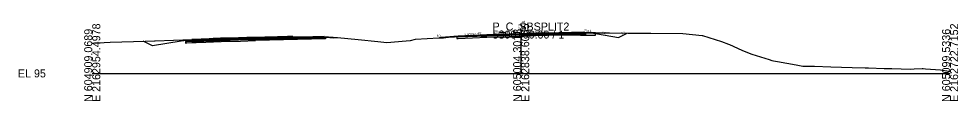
# Model space of a CAD drawing. Extents: x -26 to 1303, y -10 to 12033.
# Drawn here: x -25.7 to 302.8, y 10490.3 to 10518.4 of the extents above; entities that cross this region are included whole.
import ezdxf

# ---------------------------------------------------------------- set-up
doc = ezdxf.new("R2010")
doc.units = 0
for name, color, linetype in [('RD_GPK_XS_Cell', 7, 'Continuous'), ('RD_XS_Base', 7, 'Continuous'), ('RD_XS_ExGround', 7, 'Continuous'), ('RD_XS_ExPaveRet', 7, 'Continuous'), ('RD_XS_Greenside', 7, 'Continuous'), ('RD_XS_Pave', 7, 'Continuous'), ('RD_XS_PaveOvlay_CP', 7, 'Continuous'), ('RD_XS_TieSlope', 7, 'Continuous'), ('RD_XS_TX_Elev_EX', 7, 'Continuous'), ('RD_XS_TX_Elev_PR', 7, 'Continuous'), ('RD_XS_TX_ShdSlope', 7, 'Continuous'), ('RD_XS_TX_Slope', 7, 'Continuous')]:
    doc.layers.add(name, color=color, linetype=linetype)

msp = doc.modelspace()

# ---------------------------------------------------------------- linework, layer by layer
at = {"layer": 'RD_GPK_XS_Cell'}
for p, q in [((150, 10500), (150, 10515)), ((0, 10500), (150, 10500)), ((150, 10500), (300, 10500))]:
    msp.add_line(p, q, dxfattribs=at)
at = {"layer": 'RD_XS_Base'}
for p, q in [((138, 10513.16), (128, 10512.76)), ((136, 10513.08), (136, 10513.08)), ((150, 10513.49), (138, 10513.16)), ((150, 10513.49), (172, 10514.11)), ((150, 10512.99), (150, 10513.65)), ((150, 10513.65), (150, 10513.65)), ((150, 10513.65), (150, 10513.65)), ((150, 10513.65), (150, 10513.49)), ((172.5, 10513.62), (150, 10512.99)), ((150, 10513.49), (150, 10513.49)), ((150, 10512.99), (150, 10513.49)), ((150, 10513.49), (150, 10513.49)), ((150, 10513.49), (150, 10513.49)), ((162, 10513.83), (162, 10513.83)), ((162, 10513.83), (162, 10513.83)), ((162, 10513.33), (162, 10513.33)), ((162, 10513.33), (162, 10513.33)), ((172, 10514.11), (172, 10514.11)), ((172.5, 10514.12), (172.5, 10513.62)), ((172.5, 10514.09), (172.5, 10514.09)), ((32.89, 10511.16), (32.61, 10511.14)), ((32.61, 10511.14), (32.61, 10510.92)), ((32.61, 10510.92), (32.61, 10510.64)), ((32.61, 10510.64), (32.89, 10510.66)), ((33.11, 10511.16), (32.89, 10511.16)), ((32.89, 10510.66), (33.11, 10510.66)), ((39.76, 10511.43), (33.11, 10511.16)), ((33.11, 10510.66), (39.76, 10510.93)), ((45.11, 10511.64), (39.76, 10511.43)), ((39.76, 10510.93), (45.11, 10511.14)), ((51.86, 10511.82), (45.11, 10511.64)), ((45.11, 10511.14), (51.86, 10511.32)), ((57.11, 10511.96), (51.86, 10511.82)), ((51.86, 10511.32), (57.11, 10511.46)), ((57.11, 10511.96), (81.61, 10512.59)), ((57.11, 10511.46), (57.11, 10512.11)), ((57.11, 10512.11), (57.11, 10512.11)), ((57.11, 10512.11), (57.11, 10512.11)), ((57.11, 10512.11), (57.11, 10511.96)), ((81.61, 10512.09), (57.11, 10511.46)), ((57.11, 10511.96), (57.11, 10511.96)), ((57.11, 10511.46), (57.11, 10511.96)), ((57.11, 10511.96), (57.11, 10511.96)), ((57.11, 10511.96), (57.11, 10511.96)), ((57.11, 10511.46), (57.11, 10511.46)), ((81.11, 10512.58), (81.11, 10512.58)), ((81.11, 10512.58), (81.11, 10512.58)), ((81.11, 10512.58), (81.11, 10512.58)), ((81.11, 10512.08), (81.11, 10512.08)), ((81.11, 10512.08), (81.11, 10512.08)), ((81.61, 10512.59), (81.61, 10512.09)), ((81.61, 10512.56), (81.61, 10512.56)), ((128, 10512.76), (127.5, 10512.74)), ((127.5, 10512.74), (127.5, 10512.74)), ((127.5, 10512.74), (127.5, 10512.24)), ((127.5, 10512.24), (128, 10512.26)), ((128, 10512.76), (128, 10512.76)), ((128, 10512.26), (138, 10512.66)), ((128, 10512.26), (128, 10512.26)), ((136, 10512.58), (136, 10512.58)), ((138, 10512.66), (150, 10512.99)), ((150, 10512.99), (150, 10512.99))]:
    msp.add_line(p, q, dxfattribs=at)
at = {"layer": 'RD_XS_ExGround'}
msp.add_lwpolyline([(0, 10510.59), (0.31, 10510.6), (0.75, 10510.65), (2.1, 10510.75), (6.28, 10510.89), (18.5, 10511.33), (21.74, 10511.44), (21.83, 10511.44), (21.95, 10511.44), (34.84, 10511.82), (40.87, 10512.13), (44.85, 10512.31), (46.06, 10512.35), (48.26, 10512.39), (54.09, 10512.56), (54.59, 10512.56), (54.71, 10512.6), (54.93, 10512.6), (55.56, 10512.51), (60.37, 10512.7), (68.27, 10512.9), (70.12, 10512.95), (73.33, 10512.84), (77.68, 10512.78), (83.04, 10512.57), (84.2, 10512.5), (85.76, 10512.51), (93.03, 10511.86), (99.84, 10511.11), (102.97, 10510.85), (109.81, 10511.45), (111.29, 10511.55), (113.06, 10511.96), (121.24, 10512.5), (122.89, 10512.5), (124.61, 10512.63), (130.79, 10513.02), (136.18, 10513.43), (146.29, 10513.58), (148.31, 10513.64), (149.21, 10513.68), (151.7, 10513.92), (155.13, 10514.03), (163.26, 10514.24), (170.71, 10514.19), (171.2, 10514.18), (174.12, 10514.17), (175.96, 10514.15), (178.54, 10514.17), (179.51, 10514.17), (179.97, 10514.18), (180.31, 10514.17), (180.57, 10514.16), (180.62, 10514.16), (180.79, 10514.17), (180.89, 10514.17), (187.47, 10514.14), (191.59, 10514.13), (193.43, 10514.13), (195.37, 10514.1), (206.51, 10513.91), (213.35, 10513.24), (213.46, 10513.23), (220.1, 10511.22), (222.53, 10510.2), (222.87, 10510.06), (224.09, 10509.49), (227.38, 10508.06), (230.65, 10506.79), (236.69, 10504.83), (237.68, 10504.54), (238.19, 10504.45), (239.62, 10504.19), (246.16, 10502.97), (248.45, 10502.57), (252.53, 10502.51), (258.3, 10502.33), (265.7, 10502.08), (270.35, 10501.94), (271.42, 10501.96), (276.96, 10501.74), (279.66, 10501.76), (286.21, 10501.52), (287.41, 10501.65), (290.19, 10501.77), (290.63, 10501.73), (291.44, 10501.59), (296.67, 10501.2), (299.6, 10500.73), (299.71, 10500.73), (300, 10500.72)], dxfattribs=at)
at = {"layer": 'RD_XS_ExPaveRet'}
msp.add_line((175.96, 10513.4), (175.96, 10514.15), dxfattribs=at)
for points in [[(175.96, 10514.15), (174.12, 10514.17), (174.12, 10514.17), (171.2, 10514.18), (171.2, 10514.18), (171.2, 10514.18), (170.71, 10514.19), (170.71, 10514.19), (163.26, 10514.24), (163.26, 10514.24), (155.13, 10514.03), (155.13, 10514.03), (151.7, 10513.92), (149.21, 10513.68), (149.21, 10513.68), (148.31, 10513.64), (148.31, 10513.64), (148.31, 10513.64), (146.29, 10513.58), (136.18, 10513.43)], [(175.96, 10514.15), (174.12, 10514.17), (174.12, 10514.17), (171.2, 10514.18), (171.2, 10514.18), (170.71, 10514.19), (170.71, 10514.19), (163.26, 10514.24), (163.26, 10514.24), (155.13, 10514.03), (155.13, 10514.03), (151.7, 10513.92), (149.21, 10513.68), (149.21, 10513.68), (148.31, 10513.64), (148.31, 10513.64), (148.31, 10513.64), (146.29, 10513.58), (136.18, 10513.43)], [(136.18, 10512.68), (146.29, 10512.83), (148.31, 10512.89), (148.31, 10512.89), (148.31, 10512.89), (149.21, 10512.93), (149.21, 10512.93), (151.7, 10513.17), (155.13, 10513.28), (155.13, 10513.28), (163.26, 10513.49), (163.26, 10513.49), (170.71, 10513.44), (170.71, 10513.44), (171.2, 10513.43), (171.2, 10513.43), (171.2, 10513.43), (174.12, 10513.42), (174.12, 10513.42), (175.96, 10513.4)], [(136.18, 10512.68), (146.29, 10512.83), (148.31, 10512.89), (148.31, 10512.89), (148.31, 10512.89), (149.21, 10512.93), (149.21, 10512.93), (151.7, 10513.17), (155.13, 10513.28), (155.13, 10513.28), (163.26, 10513.49), (163.26, 10513.49), (170.71, 10513.44), (170.71, 10513.44), (171.2, 10513.43), (171.2, 10513.43), (174.12, 10513.42), (174.12, 10513.42), (175.96, 10513.4)], [(136.18, 10513.43), (136.18, 10513.43), (136.18, 10512.68)], [(136.18, 10513.43), (136.18, 10513.43), (136.18, 10512.68)], [(175.96, 10513.4), (175.96, 10514.15)], [(68.27, 10512.9), (61.21, 10512.72), (60.37, 10512.7), (56.1, 10512.53), (55.56, 10512.51), (55.49, 10512.52), (54.93, 10512.6), (54.84, 10512.6), (54.71, 10512.6), (54.64, 10512.58), (54.59, 10512.56), (54.3, 10512.56), (54.28, 10512.56), (54.09, 10512.56), (48.23, 10512.39), (47.48, 10512.37), (47.05, 10512.36), (45.63, 10512.33), (44.85, 10512.31), (42.33, 10512.2), (40.87, 10512.13), (35.23, 10511.84), (34.84, 10511.82), (34.84, 10511.69), (34.84, 10511.07), (35.23, 10511.09), (40.87, 10511.38), (42.33, 10511.45), (44.85, 10511.56), (45.63, 10511.58), (47.05, 10511.61), (47.48, 10511.62), (48.23, 10511.64), (54.09, 10511.81), (54.28, 10511.81), (54.3, 10511.81), (54.59, 10511.81), (54.64, 10511.83), (54.71, 10511.85), (54.84, 10511.85), (54.93, 10511.85), (55.49, 10511.77), (55.56, 10511.76), (56.1, 10511.78), (60.37, 10511.95), (61.21, 10511.97), (68.27, 10512.15), (68.89, 10512.17), (70.12, 10512.2), (70.12, 10512.85), (70.12, 10512.95), (68.89, 10512.92), (68.27, 10512.9)], [(68.27, 10512.9), (61.21, 10512.72), (60.37, 10512.7), (56.1, 10512.53), (55.56, 10512.51), (55.49, 10512.52), (54.93, 10512.6), (54.84, 10512.6), (54.71, 10512.6), (54.64, 10512.58), (54.59, 10512.56), (54.3, 10512.56), (54.28, 10512.56), (54.09, 10512.56), (48.23, 10512.39), (47.48, 10512.37), (47.05, 10512.36), (45.63, 10512.33), (44.85, 10512.31), (42.33, 10512.2), (40.87, 10512.13), (35.23, 10511.84), (34.84, 10511.82), (34.84, 10511.69), (34.84, 10511.07), (35.23, 10511.09), (40.87, 10511.38), (42.33, 10511.45), (44.85, 10511.56), (45.63, 10511.58), (47.05, 10511.61), (47.48, 10511.62), (48.23, 10511.64), (54.09, 10511.81), (54.28, 10511.81), (54.3, 10511.81), (54.59, 10511.81), (54.64, 10511.83), (54.71, 10511.85), (54.84, 10511.85), (54.93, 10511.85), (55.49, 10511.77), (55.56, 10511.76), (56.1, 10511.78), (60.37, 10511.95), (61.21, 10511.97), (68.27, 10512.15), (68.89, 10512.17), (70.12, 10512.2), (70.12, 10512.85), (70.12, 10512.95), (68.89, 10512.92), (68.27, 10512.9)]]:
    msp.add_lwpolyline(points, dxfattribs=at)
at = {"layer": 'RD_XS_Greenside'}
for p, q in [((174, 10514.27), (184, 10512.6)), ((184, 10512.6), (187.09, 10514.14)), ((21.11, 10509.66), (17.81, 10511.31)), ((31.11, 10511.32), (21.11, 10509.66)), ((122, 10512.59), (121.44, 10512.5))]:
    msp.add_line(p, q, dxfattribs=at)
at = {"layer": 'RD_XS_Pave'}
for p, q in [((138, 10513.47), (128, 10513.07)), ((128, 10512.92), (138, 10513.32)), ((138, 10513.32), (128, 10512.92)), ((128, 10512.76), (138, 10513.16)), ((128, 10513.07), (128, 10513.07)), ((128, 10513.07), (128, 10512.92)), ((136, 10513.39), (136, 10513.39)), ((136, 10513.24), (136, 10513.24)), ((136, 10513.24), (136, 10513.24)), ((136, 10513.08), (136, 10513.08)), ((150, 10513.81), (138, 10513.47)), ((138, 10513.32), (150, 10513.65)), ((150, 10513.65), (138, 10513.32)), ((138, 10513.16), (150, 10513.49)), ((172, 10514.43), (150, 10513.81)), ((172, 10514.27), (150, 10513.65)), ((150, 10513.65), (172, 10514.27)), ((150, 10513.49), (172.5, 10514.12)), ((150, 10513.81), (150, 10513.81)), ((150, 10513.65), (150, 10513.65)), ((150, 10513.65), (150, 10513.65)), ((150, 10513.65), (150, 10513.49)), ((150, 10513.65), (150, 10513.65)), ((150, 10513.49), (150, 10513.65)), ((150, 10513.65), (150, 10513.65)), ((150, 10513.65), (150, 10513.65)), ((150, 10513.49), (150, 10513.49)), ((150, 10513.49), (150, 10513.49)), ((162, 10514.15), (162, 10514.15)), ((162, 10514.15), (162, 10514.15)), ((162, 10513.99), (162, 10513.99)), ((162, 10513.99), (162, 10513.99)), ((162, 10513.99), (162, 10513.99)), ((162, 10513.99), (162, 10513.99)), ((162, 10513.83), (162, 10513.83)), ((162, 10513.83), (162, 10513.83)), ((172, 10514.27), (172, 10514.43)), ((172, 10514.43), (172, 10514.43)), ((172, 10514.11), (172, 10514.27)), ((172, 10514.27), (172, 10514.27)), ((39.76, 10511.75), (33.11, 10511.48)), ((33.11, 10511.32), (39.76, 10511.59)), ((39.76, 10511.59), (33.11, 10511.32)), ((33.11, 10511.48), (33.11, 10511.41)), ((33.11, 10511.16), (39.76, 10511.43)), ((33.11, 10511.41), (33.11, 10511.32)), ((33.11, 10511.32), (33.11, 10511.25)), ((33.11, 10511.25), (33.11, 10511.16)), ((45.11, 10511.96), (39.76, 10511.75)), ((39.76, 10511.59), (45.11, 10511.8)), ((45.11, 10511.8), (39.76, 10511.59)), ((39.76, 10511.43), (45.11, 10511.64)), ((51.86, 10512.14), (45.11, 10511.96)), ((45.11, 10511.8), (51.86, 10511.98)), ((51.86, 10511.98), (45.11, 10511.8)), ((45.11, 10511.64), (51.86, 10511.82)), ((57.11, 10512.27), (51.86, 10512.14)), ((51.86, 10511.98), (57.11, 10512.11)), ((57.11, 10512.11), (51.86, 10511.98)), ((51.86, 10511.82), (57.11, 10511.96)), ((81.11, 10512.9), (57.11, 10512.27)), ((81.11, 10512.74), (57.11, 10512.11)), ((57.11, 10512.11), (81.11, 10512.74)), ((57.11, 10511.96), (81.11, 10512.58)), ((57.11, 10512.27), (57.11, 10512.27)), ((57.11, 10512.11), (57.11, 10512.11)), ((57.11, 10512.11), (57.11, 10512.11)), ((57.11, 10512.11), (57.11, 10511.96)), ((57.11, 10512.11), (57.11, 10512.11)), ((57.11, 10511.96), (57.11, 10512.11)), ((57.11, 10512.11), (57.11, 10512.11)), ((57.11, 10512.11), (57.11, 10512.11)), ((57.11, 10511.96), (57.11, 10511.96)), ((57.11, 10511.96), (57.11, 10511.96)), ((81.11, 10512.74), (81.11, 10512.9)), ((81.11, 10512.9), (81.11, 10512.9)), ((81.11, 10512.9), (81.11, 10512.9)), ((81.11, 10512.9), (81.11, 10512.9)), ((81.11, 10512.58), (81.11, 10512.74)), ((81.11, 10512.74), (81.11, 10512.74)), ((81.11, 10512.74), (81.11, 10512.74)), ((81.11, 10512.74), (81.11, 10512.74)), ((81.11, 10512.74), (81.11, 10512.74)), ((81.11, 10512.74), (81.11, 10512.74)), ((81.11, 10512.58), (81.11, 10512.58)), ((81.11, 10512.58), (81.11, 10512.58)), ((128, 10512.92), (128, 10512.92)), ((128, 10512.92), (128, 10512.76))]:
    msp.add_line(p, q, dxfattribs=at)
at = {"layer": 'RD_XS_PaveOvlay_CP'}
for p, q in [((138, 10513.47), (128, 10513.07)), ((136, 10513.39), (136, 10513.39)), ((150, 10513.81), (138, 10513.47)), ((172, 10514.43), (150, 10513.81)), ((150, 10513.81), (150, 10513.81)), ((162, 10514.15), (162, 10514.15)), ((162, 10514.15), (162, 10514.15)), ((39.76, 10511.75), (33.11, 10511.48)), ((45.11, 10511.96), (39.76, 10511.75)), ((51.86, 10512.14), (45.11, 10511.96)), ((57.11, 10512.27), (51.86, 10512.14)), ((81.11, 10512.9), (57.11, 10512.27)), ((57.11, 10512.27), (57.11, 10512.27)), ((81.11, 10512.9), (81.11, 10512.9)), ((81.11, 10512.9), (81.11, 10512.9))]:
    msp.add_line(p, q, dxfattribs=at)
at = {"layer": 'RD_XS_TieSlope'}
for p, q in [((128, 10513.07), (122, 10512.59)), ((172, 10514.43), (174, 10514.27)), ((33.11, 10511.48), (31.11, 10511.32)), ((81.11, 10512.9), (85.76, 10512.51))]:
    msp.add_line(p, q, dxfattribs=at)

# ---------------------------------------------------------------- texts
at = {"layer": 'RD_GPK_XS_Cell'}
for s, p in [('E 2162954.4978', (2.8, 10490)), ('E 2162838.6065', (152.8, 10490)), ('E 2162722.7152', (302.8, 10490)), ('N 604909.0689', (0, 10490)), ('N 605004.3013', (150, 10490)), ('N 605099.5336', (300, 10490))]:
    msp.add_text(s, height=2.8, rotation=90, dxfattribs=at).set_placement(p)
for s, p in [('P_C_SBSPLIT2', (140, 10515)), ('5300+00.00 / 1', (140, 10512.2)), ('EL 95', (-26, 10498.6))]:
    msp.add_text(s, height=2.8, dxfattribs=at).set_placement(p)
at = {"layer": 'RD_XS_TX_Elev_EX'}
msp.add_text('108.76', height=0.6, rotation=90, dxfattribs=at).set_placement((149.74, 10514.83))
at = {"layer": 'RD_XS_TX_Elev_PR'}
msp.add_text('108.81', height=1, rotation=90, dxfattribs=at).set_placement((151.35, 10514.35))
at = {"layer": 'RD_XS_TX_ShdSlope'}
msp.add_text('12.5:1', height=0.75, rotation=355.4261, dxfattribs=at).set_placement((171.75, 10514.74))
at = {"layer": 'RD_XS_TX_Slope'}
for s, rotation, p in [('6:1', 9.4623, (120.55, 10512.8)), ('0.040 FT./FT.', 2.2906, (130.15, 10513.28)), ('0.030 FT./FT.', 1.7184, (140.24, 10513.78)), ('0.030 FT./FT.', 1.7184, (153.16, 10514.07)), ('6:1', 350.5358, (178.13, 10513.95)), ('2:1', 26.5651, (185.19, 10513.6))]:
    msp.add_text(s, height=0.75, rotation=rotation, dxfattribs=at).set_placement(p)

doc.saveas('drawing.dxf')
